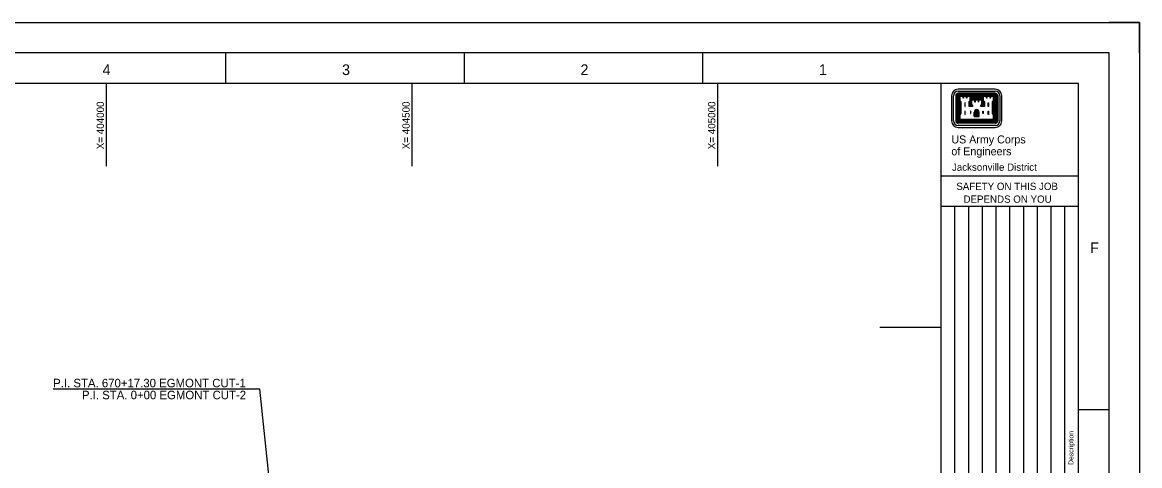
# Model space of a CAD drawing. Extents: x 401290 to 405690, y 1190598 to 1193998.
# Drawn here: x 403862 to 405690, y 1193274 to 1193998 of the extents above; entities that cross this region are included whole.
import ezdxf

# ---------------------------------------------------------------- set-up
doc = ezdxf.new("R2010")
doc.units = 0
for name, color, linetype in [('G-ANNO-NPLT', 7, 'Continuous'), ('G-ANNO-TEXT-LOGO', 7, 'Continuous'), ('G-ANNO-TEXT-TTLB', 7, 'Continuous'), ('G-ANNO-TTLB', 7, 'Continuous'), ('V-ALGN-TEXT', 7, 'Continuous'), ('V-TOPO-COOR-STAT', 7, 'Continuous')]:
    doc.layers.add(name, color=color, linetype=linetype)

msp = doc.modelspace()

# ---------------------------------------------------------------- linework, layer by layer
at = {"layer": 'G-ANNO-NPLT'}
msp.add_lwpolyline([(401290, 1193998.4), (405690, 1193998.4), (405690, 1190598.4), (401290, 1190598.4)], close=True, dxfattribs=at)
msp.add_lwpolyline([(405690, 1193948.4), (405690, 1193998.4), (405640, 1193998.4)], dxfattribs=at)
at = {"layer": 'G-ANNO-TEXT-LOGO'}
for p, q in [((405382.4, 1193878.3), (405382.4, 1193837.3)), ((405385.6, 1193837.3), (405385.6, 1193878.3)), ((405389.1, 1193878.3), (405389.1, 1193837.3)), ((405390, 1193878.3), (405390, 1193837.3)), ((405390.8, 1193878.3), (405390.8, 1193837.3)), ((405391.7, 1193878.3), (405391.7, 1193837.3)), ((405392.6, 1193878.3), (405392.6, 1193837.3)), ((405453.9, 1193889), (405393.1, 1193889)), ((405393.1, 1193885.8), (405453.9, 1193885.8)), ((405453.9, 1193882.4), (405393.1, 1193882.4)), ((405453.9, 1193881.5), (405393.1, 1193881.5)), ((405453.9, 1193880.6), (405393.1, 1193880.6)), ((405453.9, 1193879.8), (405393.1, 1193879.8)), ((405453.9, 1193878.9), (405393.1, 1193878.9)), ((405393.5, 1193878.3), (405393.5, 1193837.6)), ((405394.3, 1193878.3), (405394.3, 1193838.5)), ((405414.2, 1193878.1), (405432.8, 1193878.1)), ((405414.2, 1193877.2), (405432.8, 1193877.2)), ((405414.2, 1193876.4), (405432.8, 1193876.4)), ((405414.2, 1193875.5), (405432.8, 1193875.5)), ((405452.7, 1193878.3), (405452.7, 1193838.5)), ((405453.5, 1193878.3), (405453.5, 1193837.6)), ((405454.4, 1193878.3), (405454.4, 1193837.3)), ((405455.3, 1193878.3), (405455.3, 1193837.3)), ((405456.1, 1193878.3), (405456.1, 1193837.3)), ((405457, 1193878.3), (405457, 1193837.3)), ((405457.9, 1193878.3), (405457.9, 1193837.3)), ((405461.3, 1193878.3), (405461.3, 1193837.3)), ((405464.6, 1193837.3), (405464.6, 1193878.3)), ((405395, 1193869.6), (405395, 1193848.6)), ((405395.9, 1193868.7), (405395.9, 1193849.6)), ((405414.2, 1193874.6), (405432.8, 1193874.6)), ((405414.2, 1193873.8), (405432.8, 1193873.8)), ((405414.2, 1193872.9), (405432.8, 1193872.9)), ((405451.1, 1193868.7), (405451.1, 1193849.6)), ((405452, 1193869.5), (405452, 1193848.7)), ((405419.5, 1193844.4), (405419.5, 1193851.1)), ((405419.5, 1193844.4), (405427.5, 1193844.4)), ((405420.3, 1193844.4), (405420.3, 1193851.1)), ((405421.2, 1193844.4), (405421.2, 1193851.1)), ((405422.1, 1193844.4), (405422.1, 1193851.1)), ((405422.9, 1193844.4), (405422.9, 1193851.1)), ((405424.1, 1193844.4), (405424.1, 1193851.1)), ((405424.9, 1193844.4), (405424.9, 1193851.1)), ((405425.8, 1193844.4), (405425.8, 1193851.1)), ((405426.7, 1193844.4), (405426.7, 1193851.1)), ((405427.5, 1193844.4), (405427.5, 1193851.1)), ((405453.9, 1193836.7), (405393.1, 1193836.7)), ((405453.9, 1193835.9), (405393.1, 1193835.9)), ((405453.9, 1193835), (405393.1, 1193835)), ((405453.9, 1193834.1), (405393.1, 1193834.1)), ((405453.9, 1193833.3), (405393.1, 1193833.3)), ((405453.9, 1193829.8), (405393.1, 1193829.8)), ((405393.1, 1193826.5), (405453.9, 1193826.5)), ((405453.5, 1193837.6), (405393.5, 1193837.6)), ((405452.7, 1193838.5), (405394.3, 1193838.5))]:
    msp.add_line(p, q, dxfattribs=at)
for points in [[(405395, 1193878.3), (405395, 1193870.4), (405396.7, 1193868.7), (405396.7, 1193849.6), (405395, 1193847.8), (405395, 1193839.1), (405452, 1193839.1), (405452, 1193847.8), (405450.2, 1193849.6), (405450.2, 1193868.7), (405452, 1193870.4), (405452, 1193878.3), (405444.5, 1193878.3), (405438.7, 1193878.3), (405433.3, 1193878.3), (405433.3, 1193870.4), (405435.2, 1193868.7), (405435.2, 1193861.7), (405431, 1193861.7), (405431, 1193862.4), (405432.8, 1193864.2), (405432.8, 1193872), (405425.3, 1193872), (405419.5, 1193872), (405414.2, 1193872), (405414.2, 1193864.2), (405416, 1193862.4), (405416, 1193861.7), (405411.8, 1193861.7), (405411.8, 1193868.7), (405413.6, 1193870.4), (405413.6, 1193878.3), (405406.1, 1193878.3), (405400.3, 1193878.3), (405395, 1193878.3)], [(405395.8, 1193877.4), (405395.8, 1193870.8), (405397.6, 1193869), (405397.6, 1193849.2), (405395.8, 1193847.4), (405395.8, 1193840), (405451.2, 1193840), (405451.2, 1193847.4), (405449.3, 1193849.2), (405449.3, 1193869), (405451.2, 1193870.8), (405451.2, 1193877.4), (405445.8, 1193877.4), (405445.8, 1193874.3), (405445.3, 1193874.3), (405445.3, 1193877.4), (405440, 1193877.4), (405440, 1193874.3), (405439.6, 1193874.3), (405439.6, 1193877.4), (405434.2, 1193877.4), (405434.2, 1193870.8), (405436, 1193869), (405436, 1193860.9), (405430.2, 1193860.9), (405430.2, 1193862.8), (405432, 1193864.6), (405432, 1193871.2), (405426.6, 1193871.2), (405426.6, 1193868.1), (405426.2, 1193868.1), (405426.2, 1193871.2), (405420.8, 1193871.2), (405420.8, 1193868.1), (405420.3, 1193868.1), (405420.3, 1193871.2), (405415, 1193871.2), (405415, 1193864.6), (405416.8, 1193862.8), (405416.8, 1193860.9), (405411, 1193860.9), (405411, 1193869), (405412.8, 1193870.8), (405412.8, 1193877.4), (405407.5, 1193877.4), (405407.5, 1193874.3), (405407, 1193874.3), (405407, 1193877.4), (405401.6, 1193877.4), (405401.6, 1193874.3), (405401.2, 1193874.3), (405401.2, 1193877.4), (405395.8, 1193877.4)], [(405404, 1193866.7), (405404, 1193860.9), (405404.6, 1193860.9), (405404.6, 1193866.7), (405404, 1193866.7)], [(405413.2, 1193868.8), (405412.7, 1193868.3), (405412.7, 1193862.6), (405414.6, 1193862.6), (405413.3, 1193863.9), (405413.3, 1193868.9)], [(405433.8, 1193868.8), (405434.3, 1193868.3), (405434.3, 1193862.6), (405432.5, 1193862.6), (405433.7, 1193863.9), (405433.7, 1193868.9)], [(405442.9, 1193866.7), (405442.9, 1193860.9), (405442.4, 1193860.9), (405442.4, 1193866.7), (405442.9, 1193866.7)], [(405404, 1193853.4), (405404, 1193847.5), (405404.6, 1193847.5), (405404.6, 1193853.4), (405404, 1193853.4)], [(405413.2, 1193853.4), (405413.2, 1193849.3), (405413.7, 1193849.3), (405413.7, 1193853.4), (405413.2, 1193853.4)], [(405433.8, 1193853.4), (405433.8, 1193849.3), (405433.3, 1193849.3), (405433.3, 1193853.4), (405433.8, 1193853.4)], [(405442.9, 1193853.4), (405442.9, 1193847.5), (405442.4, 1193847.5), (405442.4, 1193853.4), (405442.9, 1193853.4)]]:
    msp.add_lwpolyline(points, dxfattribs=at)
for centre, major_axis, start_param, end_param in [((405393.1, 1193878.3), (10.7, 0), 1.57078, 3.141576), ((405393.1, 1193878.3), (7.49, 0), 1.57078, 3.141576), ((405393.1, 1193878.3), (4.02, 0), 1.57078, 3.141576), ((405393.1, 1193878.3), (3.15, 0), 1.57078, 3.141576), ((405393.1, 1193878.3), (2.28, 0), 1.57078, 3.141576), ((405393.1, 1193878.3), (1.41, 0), 1.57078, 3.141576), ((405393.1, 1193878.3), (0.546, 0), 1.57078, 3.141576), ((405453.8, 1193878.3), (10.7, 0), 6.283169, 7.853965), ((405453.8, 1193878.3), (7.49, 0), 6.28317, 7.853966), ((405453.8, 1193878.3), (4.02, 0), 6.283169, 7.853965), ((405453.8, 1193878.3), (3.15, 0), 6.283169, 7.853965), ((405453.8, 1193878.3), (2.28, 0), 6.283169, 7.853965), ((405453.8, 1193878.3), (1.41, 0), 6.283169, 7.853965), ((405453.8, 1193878.3), (0.546, 0), 6.283169, 7.853965), ((405424.9, 1193850.7), (-5.55, 0), 4.985832, 6.214359), ((405424.9, 1193850.7), (-4.69, 0), 4.947465, 6.21436), ((405424.9, 1193850.7), (-3.82, 0), 4.947465, 6.21436), ((405424.9, 1193850.7), (-2.95, 0), 4.947465, 6.21436), ((405421.9, 1193850.7), (2.08, 0), 0.068794, 1.335689), ((405421.9, 1193850.7), (2.95, 0), 0.068794, 1.335689), ((405421.9, 1193850.7), (3.82, 0), 0.068795, 1.335689), ((405424.9, 1193850.7), (-2.08, 0), 4.947465, 6.214359), ((405421.9, 1193850.7), (4.69, 0), 0.068795, 1.335689), ((405421.9, 1193850.7), (5.55, 0), 0.068795, 1.29842), ((405393.1, 1193837.3), (-10.7, 0), 6.28317, 7.853966), ((405393.1, 1193837.3), (-7.49, 0), 6.28317, 7.853966), ((405393.1, 1193837.3), (-4.02, 0), 6.28317, 7.853966), ((405393.1, 1193837.3), (-3.15, 0), 6.28317, 7.853966), ((405393.1, 1193837.3), (-2.28, 0), 6.28317, 7.853966), ((405393.1, 1193837.3), (-1.41, 0), 6.28317, 7.853966), ((405393.1, 1193837.3), (-0.546, 0), 6.28317, 7.853966), ((405453.8, 1193837.3), (4.02, 0), 4.712373, 6.28317), ((405453.8, 1193837.3), (3.15, 0), 4.712373, 6.28317), ((405453.8, 1193837.3), (2.28, 0), 4.712373, 6.28317), ((405453.8, 1193837.3), (1.41, 0), 4.712373, 6.28317), ((405453.8, 1193837.3), (0.546, 0), 4.712373, 6.28317), ((405453.8, 1193837.3), (10.7, 0), 4.712373, 6.28317), ((405453.8, 1193837.3), (-7.49, 0), 1.570781, 3.141577)]:
    msp.add_ellipse(centre, major_axis=major_axis, ratio=0.99964, start_param=start_param, end_param=end_param, dxfattribs=at)
at = {"layer": 'G-ANNO-TTLB'}
for p, q in [((404195, 1193948.4), (404195, 1193898.4)), ((404585, 1193948.4), (404585, 1193898.4)), ((404975, 1193948.4), (404975, 1193898.4)), ((405365, 1193898.4), (405365, 1190698.4)), ((405365, 1193747.2), (405590, 1193747.2)), ((405364.4, 1193698.1), (405589.4, 1193698.1)), ((405387.3, 1193698.1), (405387.3, 1192860.1)), ((405409.8, 1193698.1), (405409.8, 1192860.1)), ((405432.3, 1193698.1), (405432.3, 1192860.1)), ((405454.8, 1193698.1), (405454.8, 1192860.1)), ((405477.3, 1193698.1), (405477.3, 1192860.1)), ((405499.8, 1193698.1), (405499.8, 1192860.1)), ((405522.3, 1193698.1), (405522.3, 1192860.1)), ((405544.8, 1193698.1), (405544.8, 1192860.1)), ((405567.3, 1193698.1), (405567.3, 1192860.1)), ((405640, 1193364.9), (405590, 1193364.9))]:
    msp.add_line(p, q, dxfattribs=at)
for points in [[(401340, 1190648.4), (405640, 1190648.4), (405640, 1193948.4), (401340, 1193948.4)], [(405590, 1193898.4), (401465, 1193898.4), (401465, 1190698.4), (405590, 1190698.4)]]:
    msp.add_lwpolyline(points, close=True, dxfattribs=at)
at = {"layer": 'V-ALGN-TEXT'}
for p, q in [((404250.7, 1193398.8), (403912.8, 1193398.8)), ((404340.9, 1192548.2), (404250.7, 1193398.8))]:
    msp.add_line(p, q, dxfattribs=at)
at = {"layer": 'V-TOPO-COOR-STAT'}
for p, q in [((404000, 1193763.4), (404000, 1193898.4)), ((404500, 1193763.4), (404500, 1193898.4)), ((405000, 1193763.4), (405000, 1193898.4)), ((405265, 1193500), (405365, 1193500))]:
    msp.add_line(p, q, dxfattribs=at)

# ---------------------------------------------------------------- texts
at = {"layer": 'G-ANNO-TEXT-TTLB'}
for s, height, p in [('US Army Corps', 13.086, (405382, 1193800.4)), ('of Engineers', 13.086, (405382, 1193781)), ('Jacksonville District', 11.9, (405383, 1193755.7)), ('SAFETY ON THIS JOB', 11.9, (405390.1, 1193724.3)), ('DEPENDS ON YOU', 11.9, (405401.9, 1193703.4))]:
    msp.add_text(s, height=height, dxfattribs=at).set_placement(p)
msp.add_text('Description', height=8, rotation=90, dxfattribs=at).set_placement((405581.6, 1193274.9))
at = {"layer": 'G-ANNO-TTLB'}
for s, p in [('4', (403993.7, 1193912.2)), ('3', (404385.4, 1193912.2)), ('2', (404775.4, 1193912.2)), ('1', (405165.4, 1193912.2)), ('F', (405608.8, 1193621.1))]:
    msp.add_text(s, height=17.5, dxfattribs=at).set_placement(p)
at = {"layer": 'V-ALGN-TEXT'}
for s, p in [('P.I. STA. 670+17.30 EGMONT CUT-1', (403912.9, 1193401.6)), ('P.I. STA. 0+00 EGMONT CUT-2', (403960, 1193382.1))]:
    msp.add_text(s, height=13.92, dxfattribs=at).set_placement(p)
at = {"layer": 'V-TOPO-COOR-STAT'}
for s, p in [('X= 404000', (403996, 1193790.9)), ('X= 404500', (404496, 1193790.9)), ('X= 405000', (404996, 1193790.9))]:
    msp.add_text(s, height=12, rotation=90, dxfattribs=at).set_placement(p)

doc.saveas('drawing.dxf')
